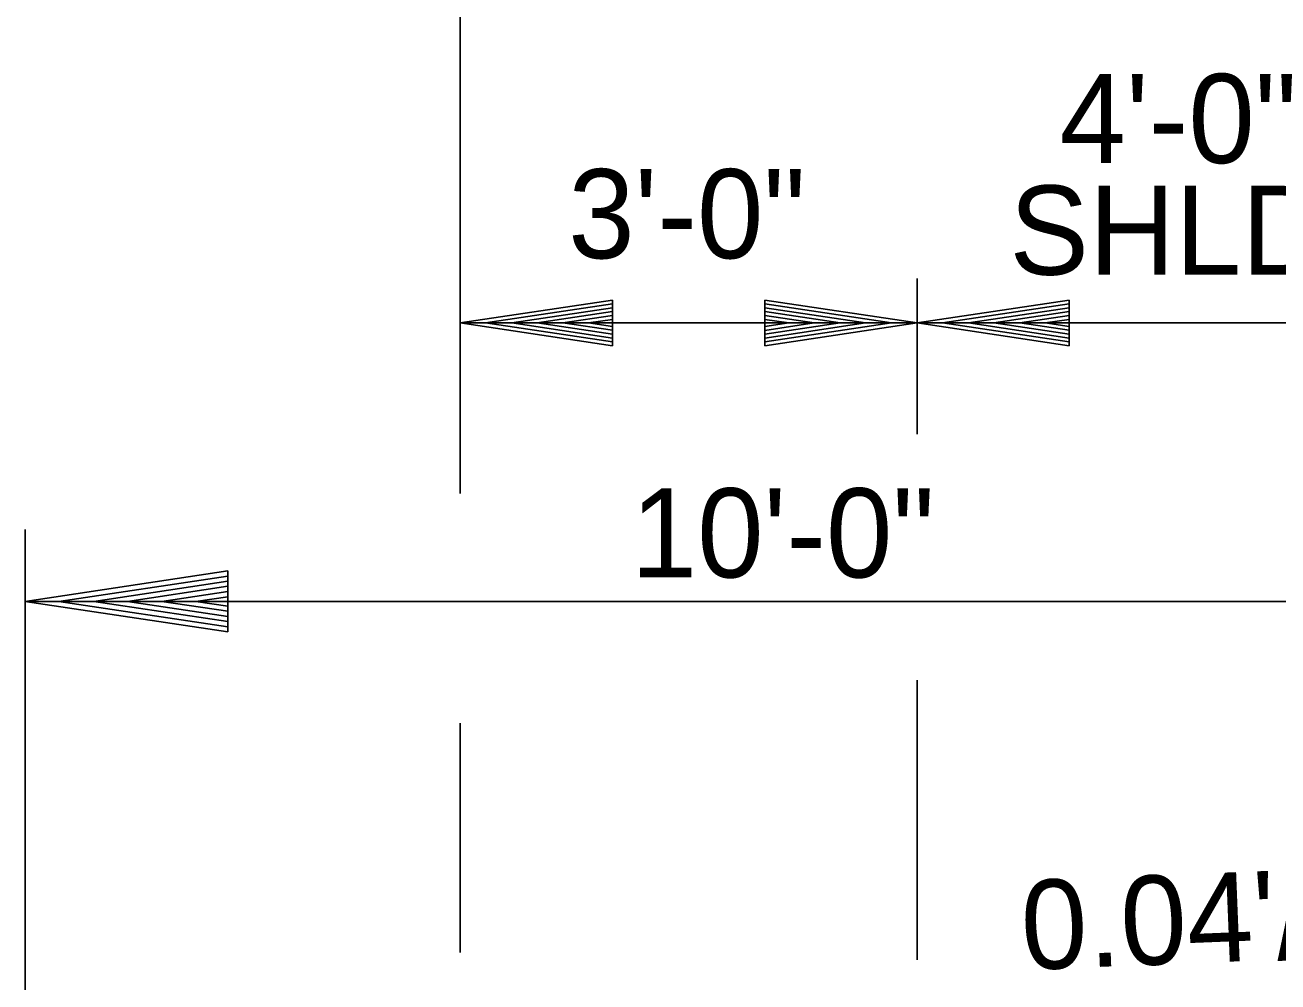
# Model space of a CAD drawing. Extents: x 1671357 to 13005564, y 567358 to 14261451.
# Drawn here: x 12758435.78 to 12758444.21, y 14259928.19 to 14259934.63 of the extents above; entities that cross this region are included whole.
import ezdxf

# ---------------------------------------------------------------- set-up
doc = ezdxf.new("R2010")
doc.units = 0
doc.layers.add('Default', color=7, linetype='Continuous')
doc.layers.add('R_Draft', color=7, linetype='Continuous')

msp = doc.modelspace()

# ---------------------------------------------------------------- linework, layer by layer
at = {"layer": 'Default'}
for p, q in [((12758438.7062, 14259931.4818), (12758438.7062, 14259942.3061)), ((12758441.7792, 14259931.8801), (12758441.7792, 14259932.9282)), ((12758441.7792, 14259932.6286), (12758445.7796, 14259932.6286)), ((12758435.7787, 14259927.0607), (12758435.7787, 14259931.2395)), ((12758435.7787, 14259930.7548), (12758445.7796, 14259930.7548)), ((12758441.7792, 14259928.3427), (12758441.7792, 14259930.2261)), ((12758438.7062, 14259928.3931), (12758438.7062, 14259929.935))]:
    msp.add_line(p, q, dxfattribs=at)
at = {"layer": 'R_Draft'}
for p, q in [((12758439.7301, 14259932.7822), (12758438.7062, 14259932.6286)), ((12758439.7301, 14259932.7565), (12758438.8772, 14259932.6286)), ((12758439.7301, 14259932.4751), (12758439.7301, 14259932.7822)), ((12758440.7554, 14259932.782), (12758441.7792, 14259932.6286)), ((12758440.7554, 14259932.782), (12758440.7554, 14259932.4749)), ((12758440.7554, 14259932.7565), (12758441.6082, 14259932.6286)), ((12758442.8031, 14259932.7822), (12758441.7792, 14259932.6286)), ((12758442.8031, 14259932.7565), (12758441.9502, 14259932.6286)), ((12758442.8031, 14259932.4751), (12758442.8031, 14259932.7822)), ((12758439.7301, 14259932.7304), (12758439.0532, 14259932.6286)), ((12758439.7301, 14259932.7048), (12758439.2238, 14259932.6286)), ((12758439.7301, 14259932.6788), (12758439.3972, 14259932.6286)), ((12758440.7554, 14259932.7304), (12758441.4322, 14259932.6286)), ((12758440.7554, 14259932.7048), (12758441.2617, 14259932.6286)), ((12758440.7554, 14259932.6782), (12758441.0883, 14259932.6286)), ((12758442.8031, 14259932.7304), (12758442.1262, 14259932.6286)), ((12758442.8031, 14259932.7048), (12758442.2968, 14259932.6286)), ((12758442.8031, 14259932.6788), (12758442.4702, 14259932.6286)), ((12758438.7062, 14259932.6286), (12758441.7792, 14259932.6286)), ((12758439.7301, 14259932.4751), (12758438.7062, 14259932.6286)), ((12758439.7301, 14259932.5006), (12758438.8772, 14259932.6286)), ((12758439.7301, 14259932.5267), (12758439.0532, 14259932.6286)), ((12758439.7301, 14259932.5524), (12758439.2238, 14259932.6286)), ((12758439.7301, 14259932.5789), (12758439.3972, 14259932.6286)), ((12758439.7301, 14259932.6526), (12758439.5683, 14259932.6286)), ((12758439.7301, 14259932.6046), (12758439.5683, 14259932.6286)), ((12758440.7554, 14259932.6526), (12758440.9171, 14259932.6286)), ((12758440.7554, 14259932.4749), (12758441.7792, 14259932.6286)), ((12758440.7554, 14259932.5783), (12758441.0883, 14259932.6286)), ((12758440.7554, 14259932.5267), (12758441.4322, 14259932.6286)), ((12758440.7554, 14259932.5006), (12758441.6082, 14259932.6286)), ((12758440.7554, 14259932.5524), (12758441.2617, 14259932.6286)), ((12758440.7554, 14259932.6046), (12758440.9171, 14259932.6286)), ((12758442.8031, 14259932.4751), (12758441.7792, 14259932.6286)), ((12758442.8031, 14259932.5006), (12758441.9502, 14259932.6286)), ((12758442.8031, 14259932.5267), (12758442.1262, 14259932.6286)), ((12758442.8031, 14259932.5524), (12758442.2968, 14259932.6286)), ((12758442.8031, 14259932.5789), (12758442.4702, 14259932.6286)), ((12758442.8031, 14259932.6526), (12758442.6414, 14259932.6286)), ((12758442.8031, 14259932.6046), (12758442.6414, 14259932.6286)), ((12758437.1438, 14259930.9597), (12758435.7787, 14259930.7548)), ((12758437.1438, 14259930.9255), (12758436.0067, 14259930.7548)), ((12758437.1438, 14259930.5502), (12758437.1438, 14259930.9597)), ((12758437.1438, 14259930.8907), (12758436.2413, 14259930.7548)), ((12758437.1438, 14259930.8565), (12758436.4687, 14259930.7548)), ((12758437.1438, 14259930.8219), (12758436.6999, 14259930.7548)), ((12758437.1438, 14259930.5502), (12758435.7787, 14259930.7548)), ((12758437.1438, 14259930.5842), (12758436.0067, 14259930.7548)), ((12758437.1438, 14259930.619), (12758436.2413, 14259930.7548)), ((12758437.1438, 14259930.6532), (12758436.4687, 14259930.7548)), ((12758437.1438, 14259930.6886), (12758436.6999, 14259930.7548)), ((12758437.1438, 14259930.7868), (12758436.9282, 14259930.7548)), ((12758437.1438, 14259930.7228), (12758436.9282, 14259930.7548))]:
    msp.add_line(p, q, dxfattribs=at)

# ---------------------------------------------------------------- texts
for s, p in [('4\'-0"', (12758442.7386, 14259933.704)), ('3\'-0"', (12758439.433, 14259933.0633)), ('SHLDR.', (12758442.4007, 14259932.9528)), ('10\'-0"', (12758439.8543, 14259930.916))]:
    msp.add_text(s, height=0.60006, dxfattribs=at).set_placement(p)
msp.add_text("0.04'/'", height=0.60006, rotation=2.29, dxfattribs=at).set_placement((12758442.4904, 14259928.2755))

doc.saveas('drawing.dxf')
